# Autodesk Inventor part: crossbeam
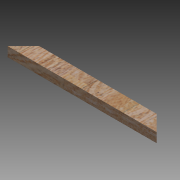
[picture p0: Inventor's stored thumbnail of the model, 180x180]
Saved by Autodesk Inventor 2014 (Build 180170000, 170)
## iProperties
Created: 2014-08
Part Number: crossbeam
Material: Generic
Document SubType Name: Modeling
Designer: Patrick Rice
Density: 1 g/cm^3
Appearance: Default
Author: Patrick Rice
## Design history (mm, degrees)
sketch "Sketch1"
  geometry: L1 (367.332, -16.534)-(-99.641, -16.534); L2 (-162.503, 46.328)-(430.194, 46.328); L3 (367.332, -16.534)-(430.194, 46.328); L4 (-162.503, 46.328)-(-99.641, -16.534)
  constraints: 8 end point, 1 horizontal, 1 parallel
  dimensions: "d0" = 88.9 distance of L1.end L2.start; "d4" = 45 deg angle of L3 L2; "d5" = 45 deg angle of L2 L4; "d6" = 466.97332 distance of L1.start L1.end
extrude "Extrusion1" new body sketch "Sketch1" distance "d2" = 38.1; taper "d3" = 0 deg
body "Solid1"
